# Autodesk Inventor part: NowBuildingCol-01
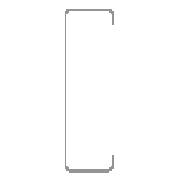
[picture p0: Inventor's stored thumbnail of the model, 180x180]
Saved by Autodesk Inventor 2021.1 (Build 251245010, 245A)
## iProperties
Created: 2020-12
Part Number: NowBuildingCol-01
Material: Generic
Document SubType Name: Modeling
Designer: BALA
Density: 1 g/cm^3
Appearance: Default
Categories: <MemberInstance><Categories><Category DisplayName="Structural Shapes" InternalName="089c4875-fa83-4c05-b084-43b9cc11f5ed" Mnemonic="GRDR"><CategoryParameter Dis
Author: BALA
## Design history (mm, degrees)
node "Start Plane"
node "End Plane"
sketch "Sketch1"
  geometry: L1 (-31.1, -101.5)-(31.1, -101.5); L2 (31.1, 101.5)-(-31.1, 101.5); L3 (-38, 94.6)-(-38, -94.6); L4 (-38, -101.5)-(38, 101.5); L5 (38, -101.5)-(-38, 101.5); L6 (-31.1, 99.6)-(31.1, 99.6); L7 (31.1, -99.6)-(-31.1, -99.6); L8 (-36.1, -94.6)-(-36.1, 94.6); L9 (38, -94.6)-(38, -82.5); L10 (38, 82.5)-(38, 94.6); L11 (36.1, 94.6)-(36.1, 82.5); L12 (36.1, -82.5)-(36.1, -94.6); L13 (36.1, -82.5)-(38, -82.5); L14 (36.1, 82.5)-(38, 82.5); A1 r 5 centre (-31.1, 94.6) between (-31.1, 99.6) and (-36.1, 94.6); A2 r 5 centre (31.1, 94.6) between (36.1, 94.6) and (31.1, 99.6); A3 r 5 centre (-31.1, -94.6) between (-36.1, -94.6) and (-31.1, -99.6); A4 r 5 centre (31.1, -94.6) between (31.1, -99.6) and (36.1, -94.6); A5 r 6.9 centre (-31.1, 94.6) between (-31.1, 101.5) and (-38, 94.6); A6 r 6.9 centre (31.1, 94.6) between (38, 94.6) and (31.1, 101.5); A7 r 6.9 centre (-31.1, -94.6) between (-38, -94.6) and (-31.1, -101.5); A8 r 6.9 centre (31.1, -94.6) between (31.1, -101.5) and (38, -94.6); 6 further points
  constraints: 28 end point, 16 point on circle, 16 tangent, 8 centre point, 6 midpoint, 6 parallel, 5 equal radius, 5 point on line, 4 perpendicular, 3 horizontal, 1 horizontal alignment, 1 vertical alignment, 1 other
  dimensions: "COL_WIDTH1" = 76 distance of point (-38, 101.5) L4.end; "COL_HEIGHT" = 203 distance of L4.end L5.start; "THICKNESS_1" = 1.9 distance between parallel lines of L2 L6; "LIP1" = 19 distance of L10.start L4.end; "LIP2" = 19 distance of L5.start L9.end; "INNERRADIUS" = 5 radius of A1; "THICKNESS_2" = 1.9 distance of L11.end L10.start; "OUTERRADIUS" = 6.9 radius of A5 (= INNERRADIUS + THICKNESS_2); "OUTERRADIUS_2" = 6.9 radius of A6 (= OUTERRADIUS); "COL_WIDTH2" = 76 distance of L9.start L3.end; "THICKNESS_3" = 1.9 distance of L3.start L8.end; "THICKNESS_4" = 1.9 distance of L12.start L9.end; "INETERNAL" = 199.2 distance between parallel lines of L7 L6 (= COL_HEIGHT - 2 x THICKNESS_1)
extrude "Body" new body sketch "Sketch1" stored distance "d17" = 2500; taper "d18" = 0 deg
node "Driven Length"
  sketch "Sketch16"
    geometry: L1 (0, 0)-(10, 0) reference
    constraints: 2 end point, 1 horizontal
  workplane "Work Plane10"
  sketch "Sketch17"
    geometry: L1 (-2, 0)-(12, 0) reference; L2 (-2, 50)-(12, 50) reference
    dimensions: "d38" = 50 distance between parallel lines of L1 L2 (derived)
body "Solid1"
other parameters: "LIP3" = 19, "LIP4" = 19, "G_OFFSET_START" = 0 [user parameter; used in 1 equation term], "d15" = 0 (computed from G_OFFSET_START), "G_OFFSET_END1" = 0 [user parameter; used in 1 equation term], "d39" = 90 deg, "OFFSET_A" = 101.5 (= 0.5 x COL_HEIGHT) [user parameter]
